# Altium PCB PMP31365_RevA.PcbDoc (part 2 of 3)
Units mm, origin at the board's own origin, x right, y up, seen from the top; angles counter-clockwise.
Board outline 134.61 x 49.53 mm, 4 copper layers (Top Layer, Layer 1, Layer 2, Bottom Layer), stack 1.787 mm thick; 183 components, 83 nets, 384 pads, 167 vias.
Unrouted connection lines stored in the file: 14.
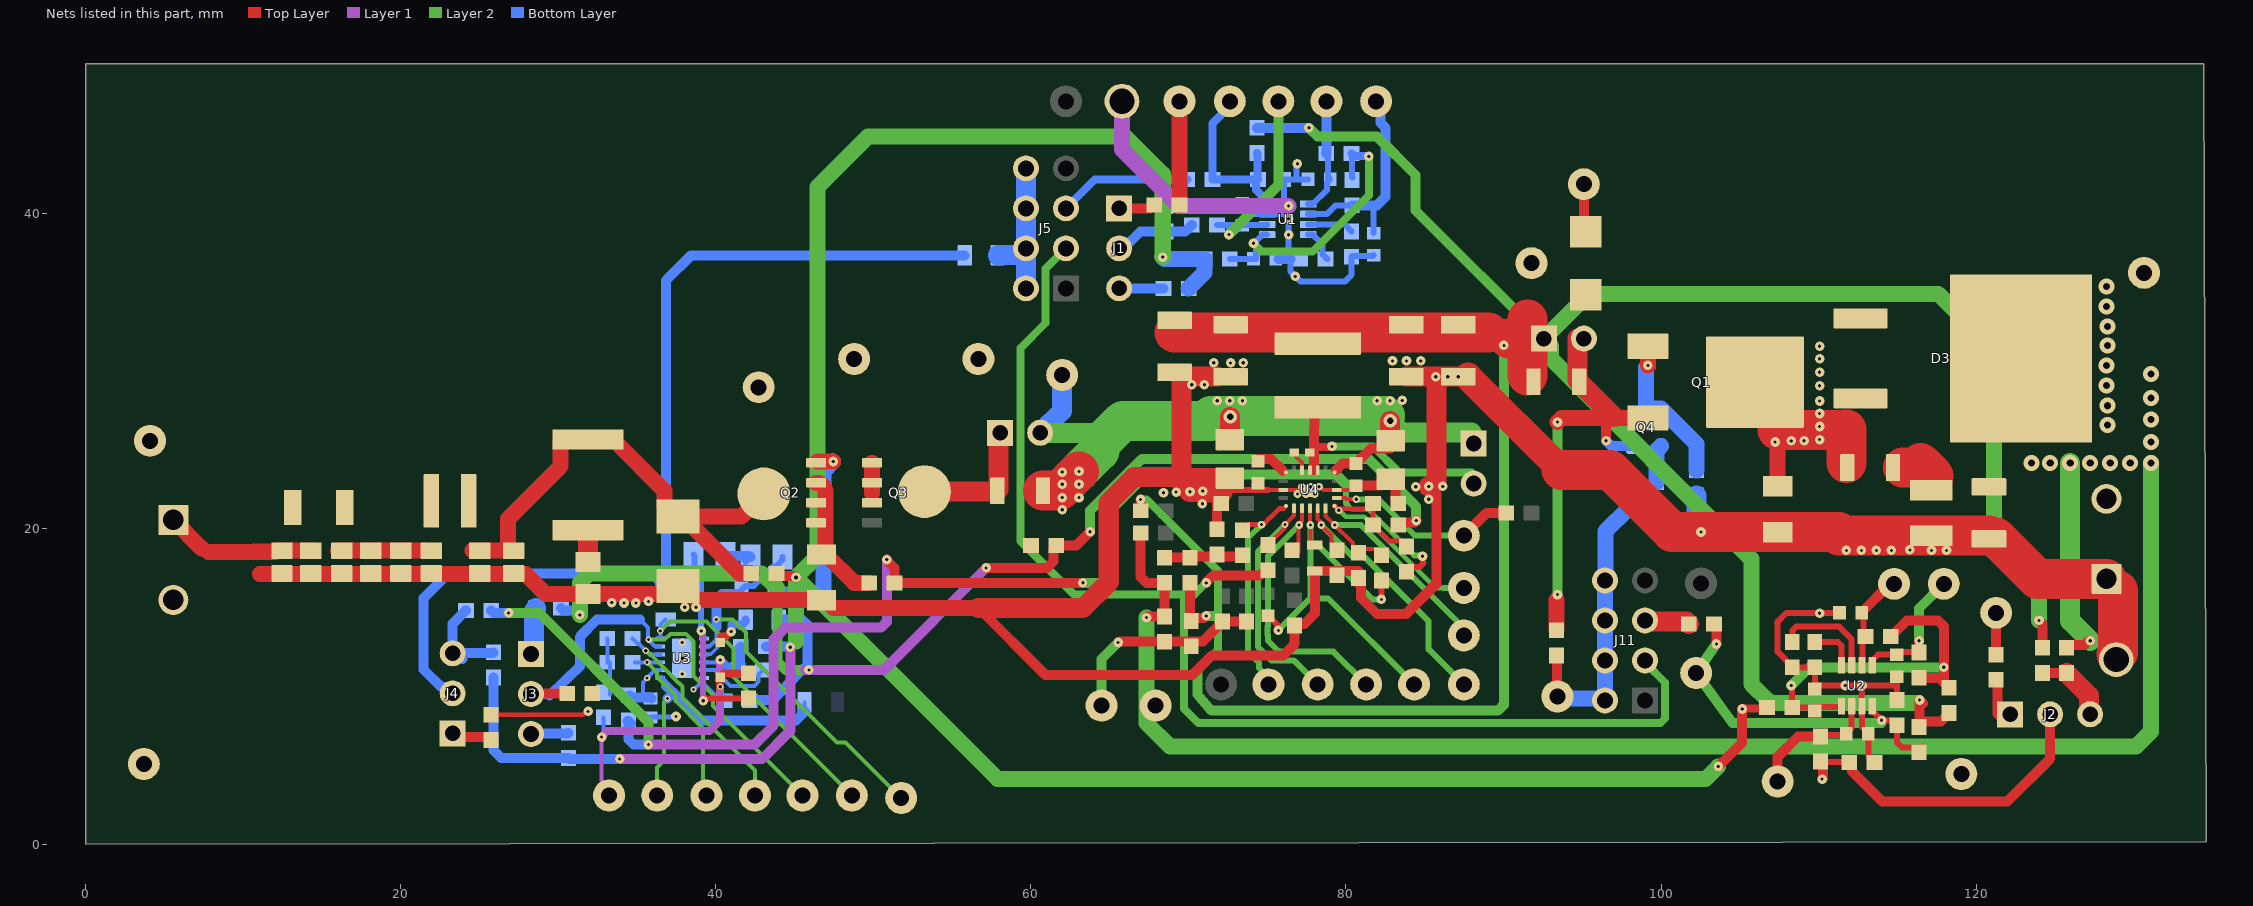
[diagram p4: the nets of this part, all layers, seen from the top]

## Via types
v1: diameter 0.61, hole 0.203, Top Layer to Bottom Layer, tented both sides, 68 vias
v2: diameter 0.61, hole 0.2, Top Layer to Bottom Layer, tented both sides, 49 vias
v3: diameter 1.016, hole 0.457, Top Layer to Bottom Layer, tented both sides, 19 vias
v4: diameter 0.5, hole 0.2, Top Layer to Bottom Layer, 9 vias
v5: diameter 0.406, hole 0.203, Top Layer to Bottom Layer, tented both sides, 9 vias
v6: diameter 0.483, hole 0.203, Top Layer to Bottom Layer, tented both sides, 7 vias
v7: diameter 0.864, hole 0.406, Top Layer to Bottom Layer, tented both sides, 3 vias
v8: diameter 0.457, hole 0.203, Top Layer to Bottom Layer, tented both sides, 1 vias
v9: diameter 0.457, hole 0.229, Top Layer to Bottom Layer, tented both sides, 1 vias
v10: diameter 0.61, hole 0.254, Top Layer to Bottom Layer, tented both sides, 1 vias

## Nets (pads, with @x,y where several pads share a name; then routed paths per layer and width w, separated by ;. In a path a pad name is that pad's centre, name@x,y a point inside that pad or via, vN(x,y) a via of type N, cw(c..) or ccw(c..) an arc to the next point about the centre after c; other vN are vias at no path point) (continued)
GND: C1.2 C2.2 C3.2 C4.2 C5.2 C7.2 C8.2 C9.2 C10.2 C11.2 C12.2 C13.2 C14.2 C15.2 C16.2 C18.1 C19.1 C20.1 C21.1 C23.1 C24.2 C25.1 C26.1 C27.1 C28.1 C29.1 C30.2 C31.1 C32.1 C33.1 C34.1 C35.1 C36.1 C37.2 C39.2 D4.2 J9.2 J10.1 R16.1 R17.1 R20.2 R21.2 R34.1 R39.1 R48.1 R52.1 R54.1 R58.1 R59.2 R60.1 R70.1 R71.1 R72.1 TP19.1 TP35.1 TP38.1 TP41.1 U1.3 U2.3 U3.7 U4.9 U4.19 U4.21 | length 285.9
  Top Layer w0.254: 75.051,22.478 U4.19@76.007,22.478 77.015,22.478 77.028,22.465 ; v4(78.292,22.678) 78.359,22.678 78.559,22.478 U4.9@79.407,22.478 80.335,22.478 80.61,22.753 C24.2@80.635,22.753
  Top Layer w0.305: R39.1@25.729,8.2 31.584,8.2 31.803,8.418 v1(31.885,8.418)
  Top Layer w0.381: v2(39.195,9.095) 39.257,9.095 39.4,9.237 C3.2@42.081,9.237 ; 72.16,22.33 72.308,22.478 75.051,22.478 ; C2.2@109.761,9.842 C2.2@109.761,10.065 ; C13.2@111.334,14.677 107.966,14.677 107.411,14.121 107.411,12.195 108.332,11.245 C14.2@108.332,11.22 C15.2@109.761,11.22 C2.2@109.761,10.065 ; v1(112.758,10.065) 112.724,8.784 U2.3@112.758,8.75 112.758,7.423 113.169,7.012 C5.2@113.169,6.987 113.169,5.543 113.533,5.179 R21.2@113.558,5.179 ; R17.1@114.973,9.142 C12.2@114.973,10.62 114.959,10.62 114.75,10.41 114.75,10.065 C2.2@109.761,10.065
  Top Layer w0.635: 56.667,14.988 60.914,10.74 70.253,10.74 71.484,11.972 76.02,11.972 76.747,12.698 R71.1@76.747,13.871 ; R72.1@71.827,19.979 C39.2@71.827,22.038 ; C30.2@74.305,22.814 74.388,22.896 C30.2@74.413,22.896 ; R71.1@76.747,13.971 77.366,13.971 78.023,14.629 C31.1@78.023,17.329 80.785,17.329 80.96,17.154 80.96,15.618 81.978,14.6 82.504,14.6 82.514,14.611 83.828,14.611 85.737,16.519 85.737,22.217 v1(85.253,22.701) ; C24.2@80.635,22.753 82.215,22.753 82.615,23.153 C29.1@82.841,23.153 83.132,22.863 83.132,21.761 83.289,21.604 R54.1@83.314,21.604
  Top Layer w1.016: 11.072,17.126 27.925,17.126 29.185,15.867 R52.1@31.885,15.867 D4.2@37.6,15.867 ; D4.2@37.6,16.368 37.892,16.368 38.781,15.479 R48.1@46.696,15.479 ; R48.1@46.971,15.479 47.463,14.988 56.667,14.988
  Top Layer w1.27: 56.667,14.988 63.308,14.988 64.941,16.621 64.941,21.686 66.556,23.302 69.439,23.302 69.519,23.222 69.556,23.222 ; C32.1@69.556,29.776 69.556,23.222 ; 70.253,29.664 C33.1@71.827,29.664 ; 72.16,22.33 70.91,22.33 70.878,22.362 70.074,22.362 69.556,22.88 69.556,23.222 ; C23.1@72.627,23.222 69.556,23.222 ; C34.1@83.828,29.664 C35.1@87.754,29.664 ; v1(85.253,22.701) 85.394,22.701 85.737,23.044 85.737,28.996 ; 100.702,19.806 v2(102.536,19.806) ; 111.06,19.806 111.296,19.57
  Top Layer w1.778: C35.1@87.754,29.664 93.671,23.747
  Top Layer w2.54: 93.671,23.747 96.761,23.747 100.702,19.806 111.296,19.806 ; 111.296,19.57 C37.2@117.169,19.57 C36.1@120.821,19.57 ; C36.1@121.28,19.45 123.899,16.83 J10.1@128.282,16.83 ; TP38.1@128.905,12.062 129.011,12.169 J10.1@129.011,16.101
  Layer 1 w0.381: v2(39.069,13.528) 39.069,13.466 39.195,13.34 v2(39.195,9.095)
  Layer 1 w1.016: TP19.1@65.778,47.149 65.778,44.103 69.369,40.512 v1(76.359,40.512)
  Bottom Layer w0.305: C7.2@35.848,8.038 35.877,8.067 37.436,8.067 v2(37.465,8.096)
  Bottom Layer w0.381: C16.2@38.578,18.381 38.657,18.301 38.657,16.967 39.069,16.555 v2(39.069,13.528) 39.069,13.466 39.133,13.402 39.133,13.104 39.198,13.038 U3.7@39.252,13.038 ; C4.2@73.662,40.449 74.127,39.983 U1.3@75.002,39.983 76.063,39.983 ; v1(76.917,43.18) 76.874,43.136 76.874,42.305 76.767,42.198 ; C8.2@77.592,42.198 76.767,42.198 ; C9.2@81.755,37.378 81.705,37.328 80.389,37.328 C10.2@80.339,37.278 80.339,36.113 79.946,35.719 77.102,35.719 76.467,36.354 76.467,37.148 76.359,37.256 v1(76.359,39.688) 76.063,39.983 ; 76.063,39.983 76.063,42.152 R16.1@76.017,42.198 76.767,42.198
  Bottom Layer w0.635: R20.2@68.58,40.487 68.58,40.512 68.751,40.683 C4.2@73.427,40.683 ; C1.2@75.702,37.148 76.467,37.148
  Bottom Layer w1.27: R60.1@102.247,22.125 102.247,20.096 v2(102.536,19.806)
  other v1: 111.691,10.065 110.066,14.648 38.017,15.028 38.735,15.028 34.17,15.301 34.925,15.301 33.386,15.324 35.72,15.403 111.772,18.639 112.724,18.639 113.677,18.639 114.629,18.639 117.169,18.639 118.122,18.639 115.803,18.67 70.889,21.604 85.253,21.88 68.416,22.3 69.216,22.339 70.099,22.362 70.91,22.402 84.437,22.678 86.15,22.701 70.21,29.156 71.014,29.156 85.705,29.664 86.467,29.664 87.13,29.664 72.675,30.543 71.611,30.556 73.484,30.556 82.952,30.668 83.841,30.668 84.753,30.668 76.785,36.036 76.359,38.682
  other v4: 76.917,22.228 77.467,22.228 78.017,22.228 77.192,22.678 77.742,22.678
HGate: Q2.4 R24.1 | length 12.7
  Top Layer w1.016: Q2.4@46.449,24.285 v2(47.451,24.285)
  Bottom Layer w1.016: R24.1@44.138,15.879 46.248,15.848 ; 45.796,15.855 46.843,16.044 46.843,23.677 v2(47.451,24.285)
NetC1_1: C1.1 R2.2 R8.2 R25.2 U1.1 | length 17.8
  Layer 2 w0.508: v1(74.127,38.138) 74.642,37.624 77.891,37.624 81.447,41.179 v2(81.447,43.656)
  Bottom Layer w0.381: R2.2@72.627,37.148 74.302,37.148 74.302,38.283 74.702,38.683 U1.1@75.002,38.683 ; R8.2@80.387,43.8 80.387,42.356 R25.2@80.429,42.314
  Bottom Layer w0.508: R8.2@80.345,43.842 80.387,43.8 80.511,43.676 81.427,43.676 v2(81.447,43.656)
NetC2_1: C2.1 R1.2 R3.2 R10.2 R26.2 U2.1 | length 24.9
  Top Layer w0.381: v2(108.267,10.065) 108.267,9.979 108.332,9.914 R1.2@108.332,8.665 109.761,8.665 109.803,8.708 111.424,8.708 111.458,8.742 U2.1@111.458,8.75
  Top Layer w0.635: R26.2@114.578,13.176 114.736,13.334 114.761,13.334 115.621,14.194 117.579,14.194 117.951,13.822 117.951,10.257 R3.2@118.269,9.939 ; R10.2@116.386,10.55 117.658,10.55 118.111,10.097 R3.2@118.269,9.939 ; R3.2@118.269,9.939 R3.2@118.269,9.914 R3.2@118.269,9.939
  Layer 2 w0.635: v2(108.267,10.065) 109.422,11.22 v2(117.951,11.22)
NetC4_1: C4.1 R14.1 TP3.1 U1.2 | length 13.6
  Layer 2 w0.635: v2(72.564,38.683) 75.707,41.827 TP3.1@75.707,47.149
  Bottom Layer w0.381: R14.1@71.814,39.283 72.564,39.283 ; v2(72.564,38.683) 72.564,39.283 ; U1.2@75.002,39.333 74.977,39.308 73.452,39.308 C4.1@73.427,39.283 72.564,39.283
NetC5_1: C5.1 R15.1 TP4.1 U2.2 | length 8.4
  Top Layer w0.381: R15.1@110.115,6.832 110.193,6.909 111.691,6.909 C5.1@111.769,6.987 111.769,7.012 112.108,7.351 U2.2@112.108,8.75
  Top Layer w0.635: TP4.1@107.411,3.969 107.411,5.543 108.7,6.832 R15.1@110.115,6.832
NetC6_2: C6.2 U3.11 | length 4.9
  Bottom Layer w0.203: C6.2@42.943,11.245 C6.2@42.968,11.245
  Bottom Layer w0.254: U3.11@39.252,11.038 39.254,11.036 39.939,11.036 40.781,10.193 40.781,10.187 40.93,10.038 42.442,10.038 42.716,10.311 42.716,10.769 C6.2@42.983,11.036
NetC7_1: C7.1 R19.1 U3.2 | length 3.9
  Bottom Layer w0.254: 35.373,9.295 35.364,10.267 v5(35.635,10.538) 36.133,11.036 36.47,11.036 U3.2@36.472,11.038
  Bottom Layer w0.635: R19.1@34.521,9.438 34.663,9.295 35.016,9.295 35.848,9.295 C7.1@35.906,9.238
NetC8_1: C8.1 R8.1 TP9.1 U1.5 | length 7.4
  Bottom Layer w0.381: U1.5@77.602,40.633 77.902,40.633 78.783,41.514 78.783,41.989 C8.1@78.992,42.198 78.869,42.322 78.869,43.718 R8.1@78.745,43.842
  Bottom Layer w0.635: R8.1@78.745,43.842 78.751,43.848 78.751,47.142 TP9.1@78.757,47.149
NetC9_1: C9.1 R25.1 TP12.1 U1.6 | length 13.5
  Bottom Layer w0.381: U1.6@77.602,39.983 78.778,39.983 79.343,40.548 R25.1@80.387,40.548 ; C9.1@81.755,38.778 81.755,40.325 81.977,40.548
  Bottom Layer w0.635: R25.1@80.387,40.548 81.977,40.548 82.514,41.085 82.514,45.469 82.182,45.801 82.182,46.881 TP12.1@81.915,47.149
NetC10_1: C10.1 U1.7 | length 2.9
  Bottom Layer w0.381: U1.7@77.602,39.333 79.909,39.333 80.339,38.903 C10.1@80.339,38.878
NetC11_1: C11.1 U1.8 | length 2.2
  Bottom Layer w0.381: U1.8@77.602,38.683 77.902,38.683 78.508,38.078 78.508,37.432 78.792,37.148 C11.1@78.817,37.148
NetC12_1: C12.1 R10.1 TP10.1 U2.5 | length 8.1
  Top Layer w0.381: U2.5@113.408,11.35 113.408,11.65 113.778,12.02 C12.1@114.973,12.02 C12.1@114.998,12.02 ; C12.1@115.173,12.195 R10.1@116.225,12.195
  Top Layer w0.635: R10.1@116.386,12.15 v2(116.386,12.9)
  Layer 2 w0.635: v2(116.386,12.9) 116.386,14.954 TP10.1@117.951,16.519
NetC13_1: C13.1 R26.1 TP13.1 U2.6 | length 6.4
  Top Layer w0.381: C13.1@112.734,14.677 112.856,14.555 112.856,13.298 R26.1@112.978,13.176 112.793,12.991 112.793,11.384 U2.6@112.758,11.35
  Top Layer w0.635: C13.1@112.734,14.677 112.734,14.702 114.552,16.519 TP13.1@114.797,16.519
NetC14_1: C14.1 U2.7 | length 6.6
  Top Layer w0.381: C14.1@108.333,12.821 108.333,13.543 108.609,13.819 111.296,13.819 112.108,13.007 U2.7@112.108,11.35
NetC15_1: C15.1 U2.8 | length 3
  Top Layer w0.381: C15.1@109.761,12.82 111.235,12.82 111.458,12.597 U2.8@111.458,11.35
NetC16_1: C16.1 R27.1 | length 2.1
  Bottom Layer w0.381: R27.1@41.88,17.897 R27.1@42.198,18.214
  Bottom Layer w0.635: C16.1@40.61,18.381 40.693,18.297 42.115,18.297 R27.1@42.198,18.214
NetC17_1: C17.1 J6.2 L3.1 U4.13 U4.14 | length 14.7
  Top Layer w0.508: 77.98,25.203 79.07,25.203 v2(79.114,25.246)
  Top Layer w0.635: 77.957,23.728 77.957,23.731 77.974,24.849 77.98,25.203 L3.1@78.017,27.729
  Layer 2 w0.508: v2(79.114,25.246) 81.706,25.246 83.37,23.583 J6.2@87.959,23.583
NetC17_2: C17.2 U4.15 | length 1.3
  Top Layer w0.254: C17.2@76.707,24.853 76.734,24.853 76.857,24.73 76.857,24.553 77.205,24.205 77.205,23.73 U4.15@77.207,23.728
NetC18_2: C18.2 C25.2 J9.1 L1.1 TP23.1 | length 10.5
  Top Layer w1.016: J9.1@5.556,20.572 7.37,18.758 ; 7.779,18.552 12.058,18.552 cw(c12.131,18.552) 12.063,18.578 cw(c12.131,18.552) 12.131,18.624 C18.2@12.454,18.624 C25.2@14.287,18.624 ; 10.676,18.578 C18.2@12.058,18.578
NetC19_2: C19.2 C20.2 C26.2 C27.2 L1.2 L2.1 | length 5.5
  Top Layer w1.016: C20.2@16.01,18.624 17.915,18.624 19.693,18.624 C26.2@21.471,18.624
NetC21_2: C21.2 C22.2 C28.2 D4.1 L2.2 Q2.5-6-7-8 R45.1 TP24.1 | length 32.6
  Top Layer w1.016: C28.2@24.562,18.624 C21.2@26.804,18.624 ; C21.2@26.805,18.624 26.805,20.644 30.143,23.982 30.143,25.538 30.285,25.68 C22.2@31.885,25.68 33.485,25.68 36.737,22.429 36.737,21.359 37.308,20.788 D4.1@37.6,20.788 D4.1@37.892,20.788 ; R45.1@42.246,17.173 41.507,17.173 D4.1@37.892,20.788 ; Q2.5-6-7-8@43.046,22.228 41.606,20.788 D4.1@37.892,20.788
NetC22_1: C22.1 R52.2 | length 2
  Top Layer w1.27: R52.2@31.885,17.899 C22.1@31.885,19.93
NetC23_2: C23.2 C24.1 C29.2 C30.1 J6.1 J7.2 R46.2 TP26.1 U4.11 U4.17 | length 47.4
  Top Layer w0.305: U4.11@79.276,23.596 79.363,23.683 79.363,23.733
  Top Layer w0.635: C30.1@74.33,24.379 C30.1@74.413,24.296 ; C30.1@74.413,24.447 75.238,24.447 75.982,23.703 ; 79.363,23.733 79.783,24.153 C24.1@80.635,24.153 80.66,24.153 80.742,24.235 80.742,24.26 81.583,25.101 C29.2@82.841,25.101
  Top Layer w1.27: C23.2@72.627,25.672 72.627,27.098 v7(72.652,27.123) ; v7(82.799,26.869) 82.799,25.646 ccw(c82.841,25.646) C29.2@82.841,25.604
  Top Layer w2.54: R46.2@60.767,22.429 61.821,22.429 v1(63.049,23.657)
  Layer 2 w1.27: J7.2@60.587,26.107 63.911,26.107 64.494,25.525 ; 82.482,27.186 v7(82.799,26.869) 83.546,26.123 J6.1@87.959,26.123
  Layer 2 w2.54: v1(63.049,23.657) 64.35,24.957 64.35,25.381 64.494,25.525 65.838,26.869 71.441,26.869 ; 71.441,27.186 82.482,27.186
  Bottom Layer w1.27: J7.2@60.587,26.107 61.968,27.488 TP26.1@61.968,30.128
  other v1: 61.984,21.226 61.984,21.991 63.049,21.991 61.984,22.843 63.049,22.843 61.984,23.612 71.827,28.139 72.627,28.139 73.427,28.139 81.978,28.139 82.799,28.139 83.578,28.164
NetC38_1: C38.1 R61.1 R62.1 R69.2 TP43.1 | length 13.1
  Top Layer w0.635: v2(65.534,12.791) 65.583,12.841 R61.1@68.491,12.841 ; R61.1@68.491,12.861 70.915,12.861 72.16,14.106 R69.2@72.16,14.131 C38.1@73.675,14.131
  Layer 2 w0.635: TP43.1@64.486,8.788 64.486,11.744 v2(65.534,12.791)
NetD1_2: D1.2 R29.2 U3.9 | length 4.8
  Top Layer w0.508: D1.2@40.273,12.791 40.319,12.837 40.319,13.185 40.653,13.185 40.951,13.483 v2(40.978,13.483)
  Bottom Layer w0.203: U3.9@39.252,12.038 39.262,12.048 39.673,12.048 40.83,13.204 v2@40.83,13.224
  Bottom Layer w0.508: v2(40.978,13.483) 40.998,13.502 40.998,13.942 41.697,13.942 41.893,14.138 R29.2@41.893,14.239
NetD2_1: D2.1 J8.2 Q1.3 Q4.2 R49.2 R56.2 | length 28.2
  Top Layer w0.635: v2(96.516,25.604) 96.516,26.575 96.983,27.043 97.035,27.095
  Top Layer w1.016: R56.2@93.357,13.572 93.357,15.496 ; v2(93.427,26.785) 93.685,27.043 96.983,27.043 ; 97.035,27.043 Q1.3@99.164,27.043
  Top Layer w1.27: J8.2@94.7,32.083 94.7,29.46 R49.2@94.807,29.353 94.807,29.323 97.035,27.095
  Layer 2 w0.635: v2(93.427,15.83) v2(93.427,26.785)
  Bottom Layer w0.635: v2(96.516,25.604) 96.868,25.252 Q4.2@98.092,25.252 Q4.2@98.092,25.417
NetD2_2: D2.2 TP20.1 | length 3.1
  Top Layer w0.635: TP20.1@95.103,41.888 95.103,38.987 ccw(c95.215,38.987) D2.2@95.215,38.875
NetD3_1: D3.1 D3.3 Q1.4 R44.1 R58.2 | length 9.6
  Top Layer w1.016: R58.2@107.411,22.706 107.411,26.281
  Top Layer w2.54: 107.411,26.281 111.296,26.281 ; R44.1@111.772,24.195 111.772,26.318
  other v1: 107.244,25.521 108.267,25.588 109.082,25.604 110.066,25.671 110.066,26.502 110.066,27.328 110.066,28.122 110.066,29.094 110.066,29.955 110.066,30.809 110.066,31.603
NetJ1_1: J1.1 R22.1 | length 2.3
  Top Layer w0.635: J1.1@65.602,40.355 67.598,40.355 67.805,40.562 R22.1@67.83,40.562
NetJ1_2: J1.2 R14.2 R20.1 | length 5.2
  Bottom Layer w0.635: J1.2@65.602,37.815 65.877,37.815 66.949,38.887 R20.1@68.58,38.887 69.793,38.887 70.189,39.283 R14.2@70.214,39.283
NetJ1_3: J1.3 R7.2 | length 2.8
  Bottom Layer w0.635: J1.3@65.602,35.275 R7.2@68.416,35.275
NetJ2_1: J2.1 R23.1 | length 2.3
  Top Layer w0.635: R23.1@121.28,10.42 121.368,10.332 121.368,8.249 J2.1@121.456,8.162
NetJ2_2: J2.2 R15.2 R21.1 | length 20.6
  Top Layer w0.381: R15.2@110.142,5.205 111.932,5.205 R21.1@111.958,5.179
  Top Layer w0.635: R15.2@110.115,5.232 110.142,5.205 110.273,5.074 110.273,4.167 v2(110.225,4.119) ; R21.1@111.958,5.179 111.983,5.179 112.141,5.021 112.141,4.61 114.052,2.699 121.988,2.699 124.706,5.417 124.706,7.78 J2.2@124.777,7.851
NetJ2_3: J2.3 R4.2 R9.2 | length 4.8
  Top Layer w0.635: R4.2@124.21,10.854 R9.2@125.742,10.854
  Top Layer w1.27: R9.2@125.742,10.854 127.173,9.423 127.173,8.307 J2.3@127.246,8.234
NetJ3_1: J3.1 R35.1 | length 3.1
  Bottom Layer w1.27: J3.1@28.269,12.063 28.459,12.253 28.459,14.793 28.574,14.908 R35.1@28.574,14.988
NetJ3_2: J3.2 R34.2 TP16.1 U3.5 | length 30.5
  Top Layer w0.635: J3.2@28.269,9.523 28.291,9.545 30.537,9.545 R34.2@30.559,9.566
  Layer 2 w0.254: v5(35.725,12.976) 36.752,12.976 37.118,13.343 38.103,13.343 38.578,12.868 38.578,10.671 39.806,9.443 39.806,8.773 TP16.1@45.498,3.082
  Bottom Layer w0.254: 35.191,14.257 35.191,14.239 35.683,13.747 35.683,12.99 36.133,12.54 36.47,12.54 U3.5@36.472,12.538 U3.5@36.47,12.536
  Bottom Layer w0.635: J3.2@28.269,9.523 29.438,9.523 ; 29.438,9.424 31.359,11.267 ; 31.359,11.366 31.359,13.156 32.459,14.257 35.191,14.257
NetJ3_3: J3.3 R30.2 | length 2.4
  Bottom Layer w0.635: J3.3@28.269,6.983 28.306,7.02 30.614,7.02 R30.2@30.651,7.057
NetJ4_1: J4.1 R39.2 | length 2.6
  Top Layer w0.635: J4.1@23.288,7.026 23.532,6.782 25.572,6.782 25.729,6.625 R39.2@25.729,6.6
NetJ4_2: J4.2 R36.2 R40.1 | length 62.6
  Bottom Layer w0.635: J4.2@23.431,9.566 23.156,9.566 22.768,9.954 22.575,9.954 21.443,11.086 21.443,15.601 23.025,17.183 35.906,17.173 36.484,16.595 36.484,16.489 36.616,16.357 R36.2@36.816,16.357 36.842,16.382 36.842,35.784 38.429,37.372 R40.1@55.794,37.372
NetJ4_3: J4.3 R37.1 R38.1 | length 5.6
  Bottom Layer w0.635: J4.3@23.288,12.17 23.288,13.983 23.953,14.648 23.953,14.673 24.111,14.83 R37.1@24.136,14.83 ; J4.3@23.715,12.106 23.745,12.136 25.863,12.136 R38.1@25.893,12.166 ; J4.3@23.909,11.741 J4.3@23.909,12.106
NetJ5_2: J5.2 J5.4 J5.6 J5.8 R40.2 | length 9.6
  Bottom Layer w1.27: R40.2@57.894,37.372 57.909,37.387 59.153,37.387 59.581,37.815 J5.4@59.684,37.815 ; J5.2@59.684,35.275 J5.4@59.684,37.815 ; J5.8@59.684,42.895 J5.6@59.684,40.355 J5.4@59.684,37.815
NetJ7_1: J7.1 Q3.5-6-7-8 R41.1 R46.1 TP21.1 | length 8.4
  Top Layer w1.27: Q3.5-6-7-8@53.239,22.366 57.805,22.366 R46.1@57.867,22.429 57.957,22.519 57.957,26.017 J7.1@58.047,26.107
NetJ11_2: J11.2 J11.4 J11.6 J11.8 R56.1 R57.1 TP39.1 | length 20.4
  Top Layer w0.635: R56.1@93.357,11.972 93.392,11.937 93.392,9.402 TP39.1@93.427,9.367
  Bottom Layer w1.016: TP39.1@93.427,9.367 93.558,9.235 96.329,9.235 J11.2@96.451,9.114 J11.4@96.451,11.654 J11.6@96.451,14.194 J11.8@96.451,16.734 ; J11.8@96.471,16.734 96.471,19.849 97.983,21.36 R57.1@99.707,21.36
NetQ1_1: Q1.1 Q4.3 R60.2 | length 9.8
  Top Layer w1.016: v2(99.164,30.387) Q1.1@99.164,31.603
  Bottom Layer w1.016: v2(99.164,30.387) 99.042,30.264 Q4.3@99.042,27.652 99.992,27.652 102.247,25.397 R60.2@102.247,23.725
NetQ2_1: Q2.1 Q2.2 Q2.3 Q3.1 Q3.2 Q3.3 R43.1 R48.2 TP25.1 | length 10.3
  Top Layer w1.016: Q2.3@46.366,22.932 cw(c46.366,22.327) 46.971,22.327 46.971,18.379 48.771,16.579 R43.1@49.735,16.579 ; 49.919,22.297 Q3.2@49.919,22.932 Q3.1@49.919,24.202
NetQ4_1: Q4.1 R57.2 | length 2.4
  Bottom Layer w1.016: R57.2@99.707,22.96 99.707,24.967 Q4.1@99.992,25.252
NetR5_1: R5.1 R11.2 R16.2 TP1.1 U1.4 | length 11.6
  Bottom Layer w0.508: TP1.1@72.627,47.149 72.627,46.832 71.529,45.733 R11.2@71.529,42.198 R16.2@74.417,42.198 ; R5.1@74.362,43.869 74.389,43.842 74.389,42.226 R16.2@74.417,42.198 ; U1.4@74.637,40.799 74.637,41.187 74.476,41.348 74.463,41.359 74.451,41.371 74.302,41.52 74.302,42.084 R16.2@74.417,42.198
NetR6_1: R6.1 R12.2 R17.2 TP2.1 U2.4 | length 22.1
  Top Layer w0.381: U2.4@113.408,8.75 113.408,8.45 v1(114.007,7.851) 114.689,7.851 114.973,7.567 R17.2@114.973,7.542 114.973,6.457 115.305,6.125 116.566,6.125 R6.1@116.625,6.184
  Top Layer w0.635: R12.2@103.364,13.971 103.517,13.819 v2(103.517,12.7)
  Layer 2 w0.635: v2(103.517,12.7) TP2.1@102.235,10.854 104.535,7.67 v1@114.007,7.67
NetR18_1: R18.1 U3.12 | length 3.3
  Bottom Layer w0.254: v5(38.578,9.806) 38.619,9.806 38.999,10.185 39.225,10.185 ; U3.12@39.252,10.538 39.227,10.538 39.225,10.536 39.225,10.185 ; R18.1@41.008,9.36 40.312,9.36 40.292,9.34 40.189,9.443 39.968,9.443 39.225,10.185
NetR22_2: R22.2 TP8.1 | length 6.6
  Top Layer w1.016: R22.2@69.43,40.562 TP8.1@69.43,47.149
NetR23_2: R23.2 TP11.1 | length 2.7
  Top Layer w0.635: R23.2@121.28,12.02 TP11.1@121.28,14.677
NetR24_2: R24.2 R27.2 TP6.1 U3.8 | length 25.9
  Layer 2 w0.254: v5(40.024,14.257) 41.067,14.257 41.906,13.418 41.906,12.228 47.684,6.45 48.238,6.45 TP6.1@51.764,2.923
  Bottom Layer w0.254: U3.8@39.252,12.538 39.254,12.54 39.591,12.54 40.024,12.973 40.024,13.747
  Bottom Layer w0.381: R24.2@41.632,16.044 41.632,16.129 41.891,16.389 42.404,16.389 43.62,17.605 43.785,17.605 44.23,18.049 R27.2@44.23,18.214
  Bottom Layer w0.635: 40.024,13.747 v5(40.024,14.257) 40.024,15.507 40.396,15.879 R24.2@41.499,15.879
NetR28_1: R28.1 TP7.1 U3.1 | length 18.3
  Layer 2 w0.254: TP7.1@36.276,3.082 36.276,4.862 36.707,5.294 36.707,9.013 36.926,9.232 v5(36.926,9.238)
  Bottom Layer w0.254: R28.1@45.297,8.465 45.62,8.788 R28.1@45.62,8.988
  Bottom Layer w0.381: U3.1@36.472,10.538 36.526,10.538 36.844,10.22 36.844,10.038
  Bottom Layer w0.635: 36.844,10.038 37.273,9.61 37.299,9.61 ; v5(36.926,9.238) 37.299,9.61 ; R28.1@45.665,8.418 45.083,7.837 44.51,7.837 44.507,7.839 39.069,7.839 37.299,9.61
NetR31_2: R31.2 R32.1 R33.1 | length 3.5
  Bottom Layer w0.254: R32.1@33.105,11.538 R33.1@33.105,13.038 ; R31.2@33.264,9.503 R32.1@33.264,11.538
NetR32_2: R32.2 TP14.1 U3.3 | length 11.6
  Layer 2 w0.254: v5(35.635,11.538) 36.276,10.898 36.276,10.607 37.137,9.746 37.434,9.448 37.434,9.093 39.195,7.333 39.195,3.286 TP14.1@39.4,3.082
  Bottom Layer w0.254: R32.2@34.864,11.538 v5(35.635,11.538) U3.3@36.472,11.538
NetR33_2: R33.2 TP15.1 U3.4 | length 14.3
  Layer 2 w0.254: v5(35.545,12.263) 35.586,12.263 35.803,12.046 35.846,12.046 36.707,11.185 36.707,11.158 37.632,10.233 37.644,10.233 37.878,9.999 37.878,9.26 42.478,4.661 TP15.1@42.478,3.082
  Bottom Layer w0.254: R33.2@34.705,13.038 35.053,12.69 35.129,12.69 35.781,12.038 U3.4@36.472,12.038
NetR36_1: R36.1 TP17.1 U3.6 | length 19.6
  Layer 2 w0.254: v5(36.472,13.528) 37.081,14.137 39.391,14.137 41.116,12.412 41.116,10.595 TP17.1@48.629,3.082
  Bottom Layer w0.254: U3.6@36.291,13.038 U3.6@36.472,13.038 36.472,13.934 36.795,14.257 R36.1@36.816,14.257
NetR42_1: R42.1 R47.1 R54.2 TP31.1 U4.7 | length 16.8
  Top Layer w0.305: U4.7@79.276,21.459 79.545,21.19 v9(79.545,21.178) 79.586,21.178 79.689,21.281 81.391,21.281 R54.2@81.714,21.604 R42.1@81.714,20.254 81.739,20.254 82.754,19.238 83.518,19.238 83.841,18.916 R47.1@83.841,18.891
  Layer 2 w0.305: v9(79.545,21.178) 79.586,21.178 79.99,20.774 81.157,20.774 85.674,16.258 86.15,16.258
  Layer 2 w0.381: 86.15,16.258 TP31.1@87.483,16.258
NetR50_2: R50.2 TP30.1 U4.3 | length 18.4
  Top Layer w0.254: R50.2@76.989,18.529 76.989,20.215 v6(77.028,20.254) 77.028,20.315 77.207,20.495 U4.3@77.207,21.328
  Layer 2 w0.381: v6(77.028,20.254) 75.051,18.277 75.051,13.854 75.034,13.838 75.034,13.28 75.051,13.264 75.051,12.908 75.746,12.213 79.199,12.213 TP30.1@81.282,10.13
NetR51_2: R51.2 TP32.1 U4.1 | length 14.5
  Top Layer w0.254: 76.066,21.308 76.066,21.335 U4.1@76.189,21.459 U4.1@76.189,21.459
  Top Layer w0.305: R51.2@73.427,19.926 73.427,19.951 73.75,20.273 73.775,20.273 73.781,20.28 v6(74.637,20.28) 74.747,20.28 75.23,20.762 75.243,20.762 75.789,21.308 76.066,21.308
  Layer 2 w0.381: v6(74.637,20.28) 73.781,19.424 73.781,12.213 74.482,11.512 74.482,11.171 75.076,10.577 TP32.1@75.076,10.13
NetR53_2: R53.2 TP34.1 U4.8 | length 12.4
  Top Layer w0.254: U4.8@79.407,21.978 79.959,21.978 80.035,21.902 80.635,21.902 v6(80.657,21.88)
  Top Layer w0.635: TP34.1@87.483,19.57 88.941,21.028 R53.2@90.176,21.028
  Layer 2 w0.381: v6(80.657,21.88) 82.087,21.868 84.385,19.57 TP34.1@87.483,19.57
NetR55_2: R55.2 TP37.1 U4.2 | length 16.3
  Top Layer w0.254: R55.2@75.057,18.979 75.057,19.004 76.094,20.041 76.094,20.241 v8(76.132,20.28) 76.705,20.853 76.705,21.326 U4.2@76.707,21.328
  Layer 2 w0.381: v8(76.132,20.28) 74.4,18.547 74.4,12.514 75.259,11.654 76.684,11.654 TP37.1@78.207,10.13
NetR59_1: R59.1 TP33.1 U4.5 | length 17.5
  Top Layer w0.254: U4.5@78.207,21.328 78.207,20.647 78.382,20.472 78.382,20.297 v6(78.425,20.254) 79.084,19.595 79.084,19.002 R59.1@79.432,18.654
  Layer 2 w0.381: v6(78.425,20.254) 78.425,20.248 80.408,18.266 81.13,18.266 85.253,14.143 85.253,12.36 TP33.1@87.483,10.13
PAD: U3.13
  other v4: 37.862,10.788 37.862,11.788 37.862,12.788
PGOOD: J5.3 J11.3 R55.1 | length 79.9
  Top Layer w0.635: v2(71.132,16.579) 71.132,16.616 71.567,17.051 74.528,17.051 74.673,17.197 74.9,17.197 75.057,17.354 R55.1@75.057,17.379
  Layer 2 w0.508: J5.3@62.224,37.815 60.941,36.532 60.941,33.085 59.33,31.475 59.33,19.233 62.733,15.83 69.703,15.83 ; v2(71.132,16.579) 71.122,16.579 70.373,15.83 69.703,15.83 ; J11.3@99.011,11.495 100.268,10.239 100.268,7.98 99.957,7.67 70.64,7.67 69.703,8.607 69.703,15.83
RESET_1: J5.5 R11.1 | length 8.5
  Bottom Layer w0.508: J5.5@62.224,40.355 64.067,42.198 R11.1@69.929,42.198
RESET_2: J11.5 R12.1 | length 2.9
  Top Layer w1.27: J11.5@98.991,14.194 99.063,14.121 101.615,14.121 R12.1@101.764,13.971
RT: R67.1 R70.2 TP36.1 U4.6 | length 16
  Top Layer w0.254: U4.6@78.707,21.328 78.709,21.326 78.709,20.827 v6(79.282,20.254) 80.437,19.099 80.437,18.86 80.644,18.653 R70.2@80.883,18.653 ; R70.2@80.96,18.729 R67.1@82.295,18.729
  Layer 2 w0.381: v6(79.282,20.254) 80.941,20.254 TP36.1@87.483,13.712
VCC: C31.2 R67.2 R68.1 TP27.1 U4.4 | length 26.8
  Top Layer w0.254: U4.4@77.707,21.328 77.709,21.326 v6@77.709,20.287 ; C31.2@77.742,19.252 v6(77.742,20.254)
  Top Layer w0.381: R68.1@75.051,14.485 75.076,14.485 75.664,13.897 75.664,13.603 v2(75.707,13.559) ; R67.2@82.246,16.734 82.248,16.732 82.248,15.535 v2(82.251,15.533)
  Layer 2 w0.381: v2(75.707,13.559) 77.742,15.594 ; v6@77.742,20.055 77.742,18.954 ; v6(77.742,20.254) 77.762,20.234 v6@77.762,20.055 ; v2@82.289,15.528 81.662,15.528 78.237,18.954 77.742,18.954 ; TP27.1@84.326,10.13 78.862,15.594 77.742,15.594 ; 77.742,15.594 77.742,18.954
Vin_A: R1.1 R2.1 R7.1 R13.2 R30.1 R38.2 R45.2 | length 167.1
  Top Layer w0.508: v2(105.157,8.572) 105.177,8.591 106.658,8.591 R1.1@106.732,8.665
  Top Layer w0.635: R45.2@43.846,17.173 44.004,17.015 45,17.015 v10(45.086,16.929) ; v2(103.633,4.921) 105.157,6.445 v2(105.157,8.572)
  Layer 1 w0.635: v2(33.884,5.403) 42.943,5.403 44.725,7.185 v2(44.725,12.487)
  Layer 2 w0.635: v2(44.725,12.487) 45.086,12.848
  Layer 2 w1.016: 45.086,12.848 v10(45.086,16.929) ; v2(68.369,37.256) 68.369,42.522 65.964,44.926 49.665,44.926 46.46,41.721 46.46,18.304 v10(45.086,16.929) ; v2(103.633,4.921) 102.839,4.127 57.887,4.127 v10(45.086,16.929)
  Bottom Layer w0.635: R38.2@25.893,10.566 25.893,5.934 26.371,5.457 R30.1@30.651,5.457 30.704,5.403 v2(33.884,5.403) ; R13.2@43.18,12.536 44.676,12.536 v2(44.725,12.487)
  Bottom Layer w1.016: v2(68.369,37.256) 68.478,37.148 R2.1@71.027,37.148 71.027,36.287 R7.1@70.016,35.275
Vin_B: R19.2 R37.2 R43.2 R47.2 | length 87.7
  Top Layer w0.381: R47.2@83.841,17.291 83.841,17.316 84.125,17.6 84.698,17.6 84.934,17.836 84.9,17.871 84.9,18.222 v2(84.856,18.266)
  Top Layer w0.635: v2(50.852,18.052) 50.927,17.976 50.927,17.938 51.335,17.529 R43.2@51.335,16.579 63.301,16.579 v2(63.302,16.581)
  Layer 1 w0.635: v2(35.712,6.311) 42.472,6.331 43.668,7.527 43.668,13.002 44.401,13.735 50.48,13.735 50.852,14.107 v2(50.852,18.052)
  Layer 2 w0.305: 80.094,21.524 80.361,21.257 81.411,21.257 84.128,18.54
  Layer 2 w0.381: 79.99,22.843 79.99,21.628 80.094,21.524 ; 84.128,18.54 84.358,18.31 84.812,18.31 v2(84.856,18.266)
  Layer 2 w0.635: v2(26.841,14.67) 28.805,14.67 35.712,7.763 v2@35.712,6.375 ; v2(63.302,16.581) 63.304,16.579 64.486,16.579 64.941,17.034 64.941,21.071 67.338,23.468 79.364,23.468 79.99,22.843
  Bottom Layer w0.635: R37.2@25.736,14.83 25.893,14.673 26.838,14.673 v2(26.841,14.67) ; R19.2@34.399,7.817 34.449,7.817 34.61,7.655 34.455,7.655 34.455,6.627 34.771,6.311 v2(35.712,6.311)
Vin_C: R18.2 R29.1 R35.2 R41.2 R42.2 | length 81.3
  Top Layer w0.635: v2(57.157,17.529) 61.012,17.529 61.418,17.936 61.418,18.796 61.576,18.954 R41.2@61.601,18.954 62.878,18.954 63.746,19.822 v2(63.759,19.822) ; R42.2@83.314,20.254 83.472,20.411 84.341,20.411 v2(84.463,20.533)
  Layer 1 w0.635: v2@45.645,11.057 50.684,11.057 v2(57.157,17.529)
  Layer 2 w0.635: 43.892,16.259 43.912,16.259 43.912,11.564 44.098,11.378 44.419,11.057 v2@45.645,11.057 ; v2(63.759,19.822) 63.759,21.163 67.042,24.446 81.447,24.446 84.453,21.44 v2@84.453,20.495
  Layer 2 w1.016: v2(31.359,14.544) 31.359,16.579 31.954,17.174 42.886,17.174 43.798,16.361 43.819,16.34 43.892,16.267 43.892,16.259
  Bottom Layer w0.635: R35.2@30.174,14.988 30.332,14.83 31.072,14.83 v2(31.359,14.544) ; R18.2@42.156,9.095 42.196,9.134 43.608,9.134 44.51,10.036 44.51,10.084 45.564,11.138 ; R29.1@43.993,14.239 44.01,14.257 45.453,14.257 45.825,13.885 v2@45.825,11.138
  other v2: 45.906,11.057
Vout: C36.2 C37.1 D3.2 J10.2 R9.1 R44.2 R61.2 R63.2 R65.2 TP28.1 TP42.1 | length 112.2
  Top Layer w0.635: R65.2@66.966,19.797 66.966,16.951 67.338,16.579 R63.2@68.491,16.579 R61.2@68.491,14.671 ; v2(67.338,14.369) 67.409,14.441 R61.2@68.491,14.441 ; R9.1@125.742,12.454 125.742,12.479 125.899,12.637 126.876,12.637 127.139,12.9 v2(127.246,12.9)
  Top Layer w2.54: 115.373,23.897 116.521,23.897 ; 116.477,24.195 117.302,23.37
  Layer 2 w1.016: v2(67.338,14.369) 67.338,7.67 68.816,6.191 130.157,6.191 131.112,7.146 v3(131.112,24.195)
  Layer 2 w1.27: v3(125.976,24.195) 125.976,14.17 v2(127.246,12.9)
  Bottom Layer w0.635: v3@124.706,24.092 v3(124.706,24.195) ; v3@131.112,24.092 v3(131.112,24.195)
  other v3: 123.519,24.195 127.246,24.195 128.516,24.195 129.786,24.195 131.112,25.521 128.341,26.609 131.112,26.953 128.341,27.826 131.112,28.323 128.282,29.1 131.112,29.829 128.282,30.37 128.341,31.64 128.341,32.857 128.282,34.131 128.282,35.401
Vout_1: C32.2 C33.2 C34.2 C35.2 J8.1 L3.2 R3.1 R4.1 R5.2 R6.2 R49.1 R62.2 R64.1 R66.2 TP22.1 | length 206.1
  Top Layer w0.635: R64.1@66.966,21.155 v2(66.966,21.88) ; R62.2@70.105,14.232 R66.2@70.105,16.579 ; R66.2@70.105,16.581 R66.2@70.105,16.579 ; R62.2@70.141,14.194 70.287,14.34 70.987,14.34 v2(71.132,14.485) ; R66.2@70.141,16.543 R66.2@70.105,16.579 ; 116.416,7.992 v2(116.416,9.142) v2@116.625,8.934 ; R6.2@116.625,7.784 117.764,7.784 118.269,8.289 R3.1@118.269,8.314 ; v2(123.996,14.194) 124.21,13.979 R4.1@124.21,12.454
  Top Layer w2.54: 69.124,32.474 89.054,32.474 ; 90.336,32.083 91.518,32.083 ; R49.1@91.518,29.742 91.518,32.083 ; 91.518,33.303 91.518,32.083 ; J8.1@91.831,32.083 91.518,32.083
  Layer 2 w0.508: v2(66.966,21.88) 67.338,21.88 71.869,17.349 71.869,14.381 71.869,12.321 70.627,11.08
  Layer 2 w0.635: 70.627,11.08 70.564,11.016 70.564,9.504 71.45,8.462 89.651,8.462 90.023,8.834 v2(90.023,31.657) ; v2(71.132,14.485) 71.765,14.485 cw(c71.765,14.381) 71.869,14.381 ; v2(77.644,45.469) 78.187,44.926 81.958,44.926 84.421,42.464 84.421,40.225 J8.1@92.563,32.083 J8.1@93.019,31.627
  Layer 2 w1.016: J8.1@92.563,32.083 95.405,34.925 117.59,34.925 121.138,31.377 121.138,18.639 123.996,15.782 v2(123.996,14.194) ; J8.1@93.019,31.627 93.019,30.811 105.739,18.091 105.739,10.149 106.747,9.142 ; 106.982,8.955 v2@116.326,8.955
  Bottom Layer w0.635: R5.2@74.362,45.469 v2(77.644,45.469)
VS: C3.1 C6.1 D1.1 R13.1 R31.1 TP5.1 U3.10 | length 23
  Top Layer w0.508: v5(40.273,9.983) D1.1@40.273,10.591 40.519,10.837 C3.1@42.081,10.837
  Layer 1 w0.254: v2@32.745,6.763 32.745,4.036 33.218,3.563 TP5.1@33.218,3.082
  Layer 1 w0.508: v2@32.731,6.799 33.093,7.161 39.59,7.161 40.273,7.844 v5(40.273,9.983) v2(40.273,11.691)
  Bottom Layer w0.254: v2@32.865,7.002 R31.1@32.865,8.041 ; U3.10@39.252,11.538 v2@40.024,11.538
  Bottom Layer w0.508: v2(40.273,11.691) 40.301,11.691 40.735,11.257 41.162,11.257 C6.1@41.383,11.036
  Bottom Layer w0.635: C6.1@41.383,11.036 41.531,11.184 41.531,12.487 R13.1@41.58,12.536
  other v2: 32.745,6.786
VSNS: R51.1 R63.1 R66.1 R72.2 | length 5
  Top Layer w0.635: R63.1@68.491,18.179 R66.1@70.105,18.179 70.178,18.253 73.354,18.253 R51.1@73.427,18.326
pads on no net: U4.10 U4.12 U4.16 U4.18

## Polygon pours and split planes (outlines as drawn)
GND on Layer 1 "LAYER_1_GND_P024" (solid, remove dead copper, pour order 24): 0.476,47.307 cw(c1.746,47.307) 1.746,48.578 132.715,48.578 cw(c132.715,47.149) 134.144,47.149 134.144,2.064 cw(c132.715,2.064) 132.715,0.635 3.016,0.635 cw(c3.016,3.175) 0.476,3.175 0.476,28.258
PAD on Layer 1 "LAYER_1_PAD_P023" (solid, remove dead copper, pour order 23): 36.752,12.976 cw(c37.114,12.976) 37.114,13.338 38.108,13.338 cw(c38.108,13.106) 38.341,13.106 38.341,10.717 cw(c37.862,10.717) 37.862,10.238 37.123,10.238 cw(c37.249,10.736) 36.752,10.861
NetC21_2 on Top Layer "TOP_LAYER_NETC21_2_P009" (solid, remove dead copper, pour order 9): 23.431,27.94 23.431,31.968 cw(c23.911,31.816) 24.063,32.297 44.276,32.297 cw(c44.276,31.662) 44.911,31.662 44.911,18.862 cw(c44.081,18.862) 44.081,18.032 24.434,18.032 cw(c24.434,19.036) 23.431,19.065
GND on Top Layer "TOP_LAYER_GND_P025" (solid, remove dead copper, pour order 25): 69.556,0.767 65.527,0.767 cw(c65.527,1.244) 65.05,1.244 65.05,47.458 cw(c65.852,47.458) 65.852,48.26 133.408,48.26 cw(c133.408,47.942) 133.725,47.942 133.725,1.328 cw(c133.191,1.328) 133.191,0.794
GND on Top Layer "TOP_LAYER_GND_P013" (solid, remove dead copper, pour order 13): 0.732,16.369 cw(c1.536,16.369) 1.536,17.173 66.003,17.173 cw(c66.003,16.62) 66.556,16.62 66.556,1.792 cw(c65.399,1.792) 65.399,0.635 2.064,0.635 cw(c2.064,1.792) 0.907,1.792
PAD on Top Layer "TOP_LAYER_PAD_P005" (solid, remove dead copper, pour order 5): 36.667,12.976 cw(c37.029,12.976) 37.029,13.338 38.108,13.338 cw(c38.108,13.015) 38.431,13.015 38.431,10.644 cw(c38.148,10.644) 38.148,10.361 37.208,10.361 cw(c37.208,10.861) 36.707,10.861
Vout on Top Layer "TOP_LAYER_VOUT_P004" (solid, remove dead copper, pour order 4): 69.216,14.127 cw(c68.966,14.127) 68.966,13.877 66.873,13.877 cw(c66.873,14.194) 66.556,14.194 66.556,20.087 67.119,20.087 cw(c67.119,19.797) 67.409,19.797 67.409,17.529 ccw(c67.766,17.529) 67.766,17.173 68.972,17.173 cw(c68.972,16.929) 69.216,16.929
NetC18_2 on Top Layer "TOP_LAYER_NETC18_2_P006" (solid, remove dead copper, pour order 6): 0.52,27.656 0.52,31.847 cw(c1.028,31.847) 1.028,32.355 14.289,32.355 cw(c14.289,31.847) 14.797,31.847 14.797,18.586 cw(c14.289,18.586) 14.289,18.078 1.333,18.078 cw(c1.333,18.852) 0.559,18.852
NetC19_2 on Top Layer "TOP_LAYER_NETC19_2_P008" (solid, remove dead copper, pour order 8): 15.385,31.974 cw(c15.766,31.974) 15.766,32.355 22.232,32.355 cw(c22.361,31.845) 22.872,31.974 22.872,18.624 cw(c22.255,18.783) 22.096,18.166 16.255,18.166 cw(c16.255,19.036) 15.385,19.036
NetQ2_1 on Top Layer "TOP_LAYER_NETQ2_1_P010" (solid, remove dead copper, pour order 10): 47.451,23.458 47.816,23.458 ccw(c47.816,23.982) 48.34,23.982 48.34,24.787 cw(c48.815,24.787) 48.815,25.262 50.141,25.262 cw(c50.141,24.797) 50.606,24.797 50.606,21.584 cw(c50.304,21.584) 50.304,21.282 48.149,21.282 ccw(c48.149,21.091) 47.959,21.091 47.959,20.331 cw(c47.451,20.331) 47.451,19.822 45.942,19.822 cw(c45.942,20.215) 45.55,20.215 45.55,23.138 cw(c45.89,23.138) 45.89,23.478
NetJ7_1 on Top Layer "TOP_LAYER_NETJ7_1_P011" (solid, remove dead copper, pour order 11): 51.374,26.017 51.374,31.865 cw(c51.806,31.865) 51.806,32.297 64.907,32.297 cw(c64.907,31.314) 65.89,31.314 65.89,18.757 cw(c65.197,18.757) 65.197,18.064 51.888,18.064 cw(c51.888,18.578) 51.374,18.578
NetQ2_1 on Top Layer "TOP_LAYER_NETQ2_1_P014" (solid, remove dead copper, pour order 14): 48.546,24.385 49.982,24.507 ccw(c49.982,25.061) 50.535,25.061 50.535,31.681 ccw(c49.919,31.681) 49.919,32.297 47.429,32.297 ccw(c47.429,31.974) 47.106,31.974 47.106,26.946 ccw(c47.615,26.946) 47.615,26.437 47.67,26.437 cw(c47.504,25.389) 48.546,25.19
NetC23_2 on Top Layer "TOP_LAYER_NETC23_2_P015" (solid, remove dead copper, pour order 15): 71.005,24.311 ccw(c71.068,24.375) 71.132,24.311 74.58,24.311 ccw(c74.58,24.669) 74.938,24.669 74.938,28.05 ccw(c74.482,28.05) 74.482,28.506 71.342,28.506 ccw(c71.342,28.042) 70.878,28.042 70.878,24.565 ccw(c71.132,24.565) 71.132,24.311
NetC23_2 on Top Layer "TOP_LAYER_NETC23_2_P016" (solid, remove dead copper, pour order 16): 82.514,24.296 84.208,24.296 ccw(c84.208,24.598) 84.509,24.598 84.509,28.037 ccw(c84.086,28.037) 84.086,28.461 81.819,28.461 ccw(c81.819,28.305) 81.662,28.305 81.662,24.6 ccw(c81.978,24.6) 81.978,24.285
Vout_1 on Top Layer "TOP_LAYER_VOUT_1_P017" (solid, remove dead copper, pour order 17): 67.639,31.678 ccw(c68.084,31.678) 68.084,31.233 92.775,31.233 ccw(c92.775,31.498) 93.039,31.498 93.039,37.848 ccw(c92.484,37.768) 92.404,38.324 68.274,38.324 ccw(c68.274,37.689) 67.639,37.689
NetD2_1 on Top Layer "TOP_LAYER_NETD2_1_P018" (solid, remove dead copper, pour order 18): 95.331,25.604 cw(c95.331,26.785) 94.151,26.785 94.151,34.867 cw(c94.807,34.867) 94.807,35.524 95.999,35.524 cw(c95.999,34.99) 96.532,34.99 96.532,30.02 ccw(c97.2,30.02) 97.2,29.353 100.265,29.353 cw(c100.265,28.64) 100.977,28.64 100.977,26.281 cw(c100.342,26.281) 100.342,25.646 97.741,25.646 ccw(c97.741,25.604) 97.7,25.604
NetD3_1 on Top Layer "TOP_LAYER_NETD3_1_P020" (solid, remove dead copper, pour order 20): 102.882,37.848 cw(c103.358,37.848) 103.358,38.324 114.153,38.324 cw(c114.153,37.848) 114.629,37.848 114.629,26.215 cw(c114.153,26.215) 114.153,25.739 103.461,25.739 cw(c103.461,26.318) 102.882,26.318
Vout on Top Layer "TOP_LAYER_VOUT_P021" (solid, remove dead copper, pour order 21): 115.582,36.26 115.582,37.491 cw(c116.376,37.491) 116.376,38.284 132.251,38.284 cw(c131.874,37.272) 132.886,36.895 132.886,23.333 cw(c131.685,23.333) 131.685,22.132 116.736,22.132 cw(c116.736,23.333) 115.535,23.333
NetD3_1 on Layer 2 "LAYER_2_NETD3_1_P028" (solid, remove dead copper, pour order 28): 100.791,32.544 cw(c101.743,32.544) 101.743,33.496 116.599,33.496 cw(c116.599,32.505) 117.59,32.505 117.59,22.635 cw(c116.386,22.635) 116.386,21.431 106.839,21.431 cw(c106.839,22.701) 105.569,22.701 ccw(c103.346,22.701) 103.346,24.924 101.699,24.924 cw(c101.699,25.832) 100.791,25.832
Vout on Layer 2 "LAYER_2_VOUT_P026" (solid, remove dead copper, pour order 26): 133.09,19.526 ccw(c133.09,20.161) 133.725,20.161 133.725,47.29 ccw(c132.856,47.29) 132.856,48.159 120.867,48.159 ccw(c120.867,47.149) 119.856,47.149 119.856,21.749 ccw(c122.079,21.749) 122.079,19.526
NetC23_2 on Layer 2 "LAYER_2_NETC23_2_P012" (solid, remove dead copper, pour order 12): 61.424,21.243 63.449,21.243 67.774,25.568 84.176,25.568 ccw(c84.176,26.335) 84.943,26.335 84.943,30.577 ccw(c84.157,30.577) 84.157,31.363 62.059,31.363 ccw(c62.059,30.601) 61.297,30.601
GND on Bottom Layer "BOTTOM_LAYER_GND_P029" (solid, remove dead copper, pour order 29): 0.669,45.561 0.669,47.604 cw(c1.27,47.604) 1.27,48.206 133.145,48.206 cw(c133.145,47.625) 133.725,47.625 133.725,1.645 cw(c132.874,1.645) 132.874,0.794 50.545,0.794 ccw(c50.545,0.767) 50.518,0.767 cw(c50.386,0.767) 50.386,0.635 1.968,0.635 cw(c1.968,2.064) 0.539,2.064

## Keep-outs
Keep-Out Layer:
  text ".Layer_Name" at 14.656,-21.806 h1.52

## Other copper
Top Layer:
  rectangle net NetC21_2: 40.603,18.781 44.911,25.538
  rectangle net NetJ7_1: 51.374,18.629 56.65,26.017
  text ".Layer_Name" at 14.656,-21.806 h1.52
Layer 1:
  rectangle net GND: 50.313,19.05 55.887,26.303
  rectangle net GND: 39.715,19.05 46.277,25.922
Bottom Layer:
  rectangle net GND: 50.545,19.263 55.794,25.328
  rectangle net GND: 40.416,19.564 45.297,25.328
  text ".Layer_Name" at 14.656,-21.806 h1.52

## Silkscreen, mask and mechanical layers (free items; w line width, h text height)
Top Overlay:
  text "PMP31365_RevA" at 22.06,45.417 h2.03
  text ".Layer_Name" at 14.656,-21.806 h1.52
Bottom Overlay:
  text ".Layer_Name" at 14.656,-21.806 h1.52
Top Paste:
  text ".Layer_Name" at 14.656,-21.806 h1.52
Bottom Paste:
  text ".Layer_Name" at 14.656,-21.806 h1.52
Top Solder:
  text ".Layer_Name" at 14.656,-21.806 h1.52
  text ".Layer_Name" at 14.656,-21.806 h1.52
Bottom Solder:
  text ".Layer_Name" at 14.656,-21.806 h1.52
Drill Guide:
  text ".Layer_Name" at 14.656,-21.806 h1.52
M1 Board Outline:
  the board outline again, w0.254
  text ".Layer_Name" at 14.656,-21.806 h1.52
M2 Board Dimensions:
  rectangle: 3.175,-10.16 12.7,-6.985
  rectangle: 0,-6.985 3.175,-3.81
  lines w0.178: 0,-6.985 25.4,-6.985 ; 3.175,-10.16 3.175,-3.81 ; 6.35,-10.16 6.35,-3.81 ; 12.7,-10.16 12.7,-3.81 ; 19.05,-10.16 19.05,-3.81 ; 0,-10.16 0,-3.81 25.4,-3.81 25.4,-10.16 0,-10.16
  text ".Layer_Name" at 14.656,-21.806 h1.52
M3 3D STEP Top:
  text ".Layer_Name" at 14.656,-21.806 h1.52
M4 3D STEP Bottom:
  text ".Layer_Name" at 14.656,-21.806 h1.52
M5 Assembly Top:
  lines w0.254: -7.417,-23.626 160.223,-23.626 ; -7.417,-18.462 160.274,-18.462 ; -7.417,-13.297 -7.417,-28.791 94.31,-28.791 160.274,-28.791 160.274,-13.297 -7.404,-13.297 -7.404,-28.791 32.614,-28.791 ; 55.194,-28.791 55.194,-13.297 ; 87.376,-18.462 87.376,-13.297 ; 108.712,-18.462 108.712,-13.297 ; 124.511,-28.956 124.511,-23.804
  text "COMPONENTS MARKED 'DNP' SHOULD NOT BE POPULATED." at 29.299,-8.09 h1.52
  text "ASSEMBLY VARIANT:" at 29.286,-11.024 h1.52
  text ".VariantName" at 55.601,-11.024 h1.52
  text "PCB VIEWED FROM TOP SIDE" at -5.804,-16.654 h1.52
  text "BOARD #:" at 57.099,-16.654 h1.52
  text ".PRJ_Number" at 70.955,-16.654 h1.52
  text "REV:" at 92.405,-16.654 h1.52
  text ".PCB_Rev" at 99.809,-16.654 h1.52
  text "SVN REV:" at 113.69,-16.654 h1.52
  text ".VersionControl_RevNumber" at 126.543,-16.654 h1.52
  text "PLOT NAME =" at -5.804,-27.034 h1.52
  text ".plot_File_Name" at 14.656,-27.034 h1.52
  text "GENERATED    :" at 57.15,-27.034 h1.52
  text ".Print_Date" at 79.235,-27.034 h1.52
  text ".Print_Time" at 97.752,-27.034 h1.52
  text "TEXAS INSTRUMENTS" at 129.87,-27.034 h1.52
M6 Assembly Bottom:
  lines w0.254: -7.429,-18.474 160.261,-18.474 ; -7.379,-23.639 160.261,-23.639 ; 28.334,-28.969 28.334,-23.817 ; 44.133,-18.474 44.133,-13.31 ; 65.468,-18.474 65.468,-13.31 ; 97.65,-28.804 97.65,-13.31 ; 120.231,-28.804 160.249,-28.804 160.249,-13.31 -7.429,-13.31 -7.429,-28.804 58.534,-28.804 160.261,-28.804 160.261,-13.31
  text "COMPONENTS MARKED 'DNP' SHOULD NOT BE POPULATED." at 154.991,-8.077 h1.52
  text ".VariantName" at 128.473,-11.024 h1.52
  text "ASSEMBLY VARIANT:" at 154.864,-11.024 h1.52
  text ".VersionControl_RevNumber" at 26.302,-16.667 h1.52
  text "SVN REV:" at 39.154,-16.667 h1.52
  text ".PCB_Rev" at 53.035,-16.667 h1.52
  text "REV:" at 60.439,-16.667 h1.52
  text ".PRJ_Number" at 81.89,-16.667 h1.52
  text "BOARD #:" at 95.745,-16.667 h1.52
  text "PCB VIEWED FROM BOTTOM SIDE" at 158.648,-16.667 h1.52
  text "TEXAS INSTRUMENTS" at 22.974,-27.047 h1.52
  text ".Print_Time" at 55.093,-27.047 h1.52
  text ".Print_Date" at 73.609,-27.047 h1.52
  text "GENERATED    :" at 95.694,-27.047 h1.52
  text ".plot_File_Name" at 138.189,-27.047 h1.52
  text "PLOT NAME =" at 158.648,-27.047 h1.52
M9 Title Sheet:
  drawing of 63 lines, arcs and shapes, not listed
  text "1" at 35.293,466.75 h1.78
  text "2" at 136.766,466.75 h1.78
  text "3" at 238.239,466.75 h1.78
  text "4" at 339.865,466.75 h1.78
  text "5" at 441.423,466.75 h1.78
  text "6" at 542.98,466.75 h1.78
  text "7" at 644.623,466.75 h1.78
  text "8" at 746.096,466.75 h1.78
  text "A" at -11.874,405.841 h1.78
  text "A" at 793.305,405.841 h1.78
  text "B" at -11.874,278.841 h1.78
  text "B" at 793.305,278.841 h1.78
  text "C" at -11.874,151.841 h1.78
  text "C" at 793.305,151.841 h1.78
  text "D" at -11.874,24.841 h1.78
  text "D" at 793.305,24.841 h1.78
  text "PROJECT TITLE:" at 714.947,6.823 h1.14
  text ".PRJ_Title" at 716.216,3.436 h1.78
  text "DESIGNED FOR:" at 714.947,-0.823 h1.14
  text ".PRJ_Customer" at 716.216,-4.379 h1.78
  text "FILE NAME:" at 714.947,-8.443 h1.14
  text ".PCB_File_Name_No_Path" at 716.216,-11.491 h1.78
  text "Texas Instruments (TI) and/or its licensors do not warrant the accuracy or completeness of this specification" at 588.721,-15.601 h1.14
  text "ENGINEER:" at 714.947,-15.809 h1.14
  text "LAYOUT BY:" at 753.173,-15.809 h1.14
  text "or any information contained therein. TI and/or its licensors do not warrant that this design will meet" at 587.579,-18.463 h1.14
  text ".PRJ_Engineer" at 716.216,-19.746 h1.78
  text ".PCB_Layout" at 754.456,-19.746 h1.78
  text "the specifications, will be suitable for your application or fit for any particular purpose, or will operate in" at 587.579,-21.325 h1.14
  text ".Layer_Name" at 14.656,-21.806 h1.52
  text "ALTIUM DESIGNER VERSION:" at 753.173,-23.683 h1.14
  text "an implementation. TI and/or its licensors do not warrant that the design is production worthy. You should" at 587.579,-24.187 h1.14
  text "completely validate and test your design implementation to confirm the system functionality for your application." at 588.721,-27.048 h1.14
  text ".print_Scale" at 716.216,-27.069 h1.78
  text ".Application_BuildNumber" at 754.456,-27.069 h1.78
  text "1" at 35.293,-33.503 h1.78
  text "2" at 136.766,-33.503 h1.78
  text "3" at 238.239,-33.503 h1.78
  text "4" at 339.865,-33.503 h1.78
  text "5" at 441.423,-33.503 h1.78
  text "6" at 542.98,-33.503 h1.78
  text "7" at 644.623,-33.503 h1.78
  text "8" at 746.096,-33.503 h1.78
